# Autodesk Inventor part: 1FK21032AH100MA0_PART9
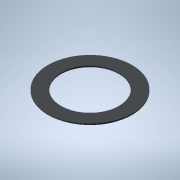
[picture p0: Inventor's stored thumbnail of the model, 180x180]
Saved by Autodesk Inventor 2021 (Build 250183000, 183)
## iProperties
Created: 2025-04
Part Number: 1FK21032AH100MA0_PART9
Material: Generic
Catalog Web Link: www.3dfindit.com
Description: -Servo synchronous motor
Document SubType Name: Modeling
Designer: psAdmin
Mass: 0.211555 g
Surface Area: 9.31012 cm^2
Volume: 0.211555 cm^3
Density: 1 g/cm^3
Appearance: PSOLRGB-212-217-219
Category: PARTsolutions
Title: 1FK21032AH100MA0_PART9
Author: Cadenas PARTsolutions
Comments: Servo synchronous motor
Sending System: PARTsolutions
Preprocessor: ST-DEVELOPER v19.3
PSOL_IDENT_0: {$CADENAS_DATA/23d-libs/siemens_ag/_cat_/12/33/1fk21032ah100ma0.prj},213 {VTYP=3D},{NB=1FK21032AH100
PSOL_IDENT_1: MA0_PART9},{LINA=1FK21032AH100MA0_PART9},{NN=1FK21032AH100MA0_PART9},{NOPRJ=TRUE},{DATE=19.08.2025 1
PSOL_IDENT_2: 4:00:27},{GEOMDATE=30.07.2025 02:02:58},{VERSION=},{LINEID=10},{WBVAR=},{WBNUMERIC=}  {NB=1FK21032AH
PSOL_IDENT_3: 100MA0_PART9},{LINA=1FK21032AH100MA0_PART9},{KT=DUMMY},{PREVIEW=../../../_pool_/d3/78/p_d211_xx_0093
PSOL_IDENT_4: 4j.png},{DESCSHORT=SIMOTICS S-1FK2 HD, SINAMICS S210 3AC 400V-480V, 0.59 Nm, 4500 rpm},{DESCLONG=SIM
PSOL_IDENT_5: OTICS S-1FK2 HD servo motor M0=0.64 Nm; PN = 0.28 kW at nN=4500 rpm (380-480 V); PN = 0.167 kW at nN=
PSOL_IDENT_6: 2500 rpm (200-240 V); with holding brake; degree of protection IP64; cylindrical shaft D14 x 30 mm;
PSOL_IDENT_7: absolute encoder 22-bit + 12-bit multiturn (encoder AM22DQC); with OCC interface; plug size M17, rot
PSOL_IDENT_8: atable; SIMOTICS S-1FK2 servomotorfor a wide range of uses in industrial environments. SIMOTICS S‑1F
PSOL_IDENT_9: K2 servomotors are compact synchronous motors with a high dynamic performance that set themselves ap
PSOL_IDENT_10: art as a result of their high power density, degree of protection and overload capability. The motor
PSOL_IDENT_11: s are available in two variants: as High Dynamic variant (highest dynamic performance as a result of
PSOL_IDENT_12: the low intrinsic moment of inertia for applications demanding a high dynamic performance with low
PSOL_IDENT_13: moved masses) - and as Compact variant (precise and stable closed-loop control for medium up to larg
PSOL_IDENT_14: e moved masses as a result of a medium intrinsic moment of inertia). SIMOTICSS‑1FK2 servomotors full
PSOL_IDENT_15: y exploit their strengths in a system with the SINAMICSS210 frequency converter and simple connectio
PSOL_IDENT_16: n using the one cable connection (OCC). Advantages include the short control and positioning times,
PSOL_IDENT_17: fast and precise correction of disturbing quantities as well as stable control with a high dynamic p
PSOL_IDENT_18: erformance. The servo motors can be configured to address a wide range of requirements. For example
PSOL_IDENT_19: with and without holding brake, IP64 or IP65 degree of protection, singleturn or multiturn absolute
PSOL_IDENT_20: encoders - to name just a few. Further, the servomotors are available in different shaft heights ext
PSOL_IDENT_21: ending from 20 to 100. A shaft sealing ring is available to achieve an IP65 degree of protection and
PSOL_IDENT_22: for subsequent mounting at the motor or as spare part. SIMOTICS - the optimum motor for each and ev
PSOL_IDENT_23: ery motion control application.},{INTNO=195125315563},{SUPPLIERALTNO=1FK2103-2AH10-0MA0},{MANUID=1FK
PSOL_IDENT_24: 21032AH100MA0},{MANUNAME=Siemens},{MANUTYPEDESC=SYNCHRONOUS MOTOR 1FK2 HD 0,64 NM},{AAU732=SIMOTICS}
PSOL_IDENT_25: ,{AAO057=S-1FK2},{AAU734=SIMOTICS S-1FK2 HD servo motor M0=0.64 Nm; PN = 0.28 kW at nN=4500 rpm (380
PSOL_IDENT_26: -480 V); PN = 0.167 kW at nN=2500 rpm (200-240 V); with holding brake; degree of protection IP64; cy
PSOL_IDENT_27: lindrical shaft D14 x 30 mm; absolute encoder 22-bit + 12-bit multiturn (encoder AM22DQC); with OCC
PSOL_IDENT_28: interface; plug size M17, rotatable;},{AAW338=SYNCHRONOUS MOTOR 1FK2 HD 0,64 NM},{AAO742=SIMOTICS},{
PSOL_IDENT_29: AAO663=4034106444723},{NOCUPEROU=1},{PRICEQUANTITY=1},{QUANTITYMIN=1},{QUANTITYINT=1},{CTN=85015100}
PSOL_IDENT_30: ,{COO=RO},{AAO676=1FK2103-2AH10-0MA0},{AAO677=Siemens AG},{ORDERUNIT=C62},{CONTENTUNIT=C62}
NB: 1FK21032AH100MA0_PART9
NT: Servo synchronous motor
NBSYN: $MANUID._PART9
LINA: 1FK21032AH100MA0_PART9
CATALOG: SIEMENS
PREVIEW: ../../../_pool_/d3/78/p_d211_xx_00934j.png
DESCSHORT: SIMOTICS S-1FK2 HD, SINAMICS S210 3AC 400V-480V, 0.59 Nm, 4500 rpm
DESCLONG: SIMOTICS S-1FK2 HD servo motor M0=0.64 Nm; PN = 0.28 kW at nN=4500 rpm (380-480 V); PN = 0.167 kW at nN=2500 rpm (200-240 V); with holding brake; degree of prot
INTNO: 195125315563
SUPPLIERALTNO: 1FK2103-2AH10-0MA0
MANUID: 1FK21032AH100MA0
MANUNAME: Siemens
MANUTYPEDESC: SYNCHRONOUS MOTOR 1FK2 HD 0,64 NM
AAU732: SIMOTICS
AAO057: S-1FK2
AAU734: SIMOTICS S-1FK2 HD servo motor M0=0.64 Nm; PN = 0.28 kW at nN=4500 rpm (380-480 V); PN = 0.167 kW at nN=2500 rpm (200-240 V); with holding brake; degree of prot
AAW338: SYNCHRONOUS MOTOR 1FK2 HD 0,64 NM
AAO742: SIMOTICS
AAO663: 4034106444723.0
NOCUPEROU: 1
PRICEQUANTITY: 1
QUANTITYMIN: 1
QUANTITYINT: 1
CTN: 85015100
COO: RO
ARTICLENO: 1FK21032AH100MA0_PART9
BOMINFO: 1FK21032AH100MA0_PART9
CREATOR: CADENAS GmbH
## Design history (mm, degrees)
feature "2025_04_17_15_06_16_0705"
body "Solid1"
